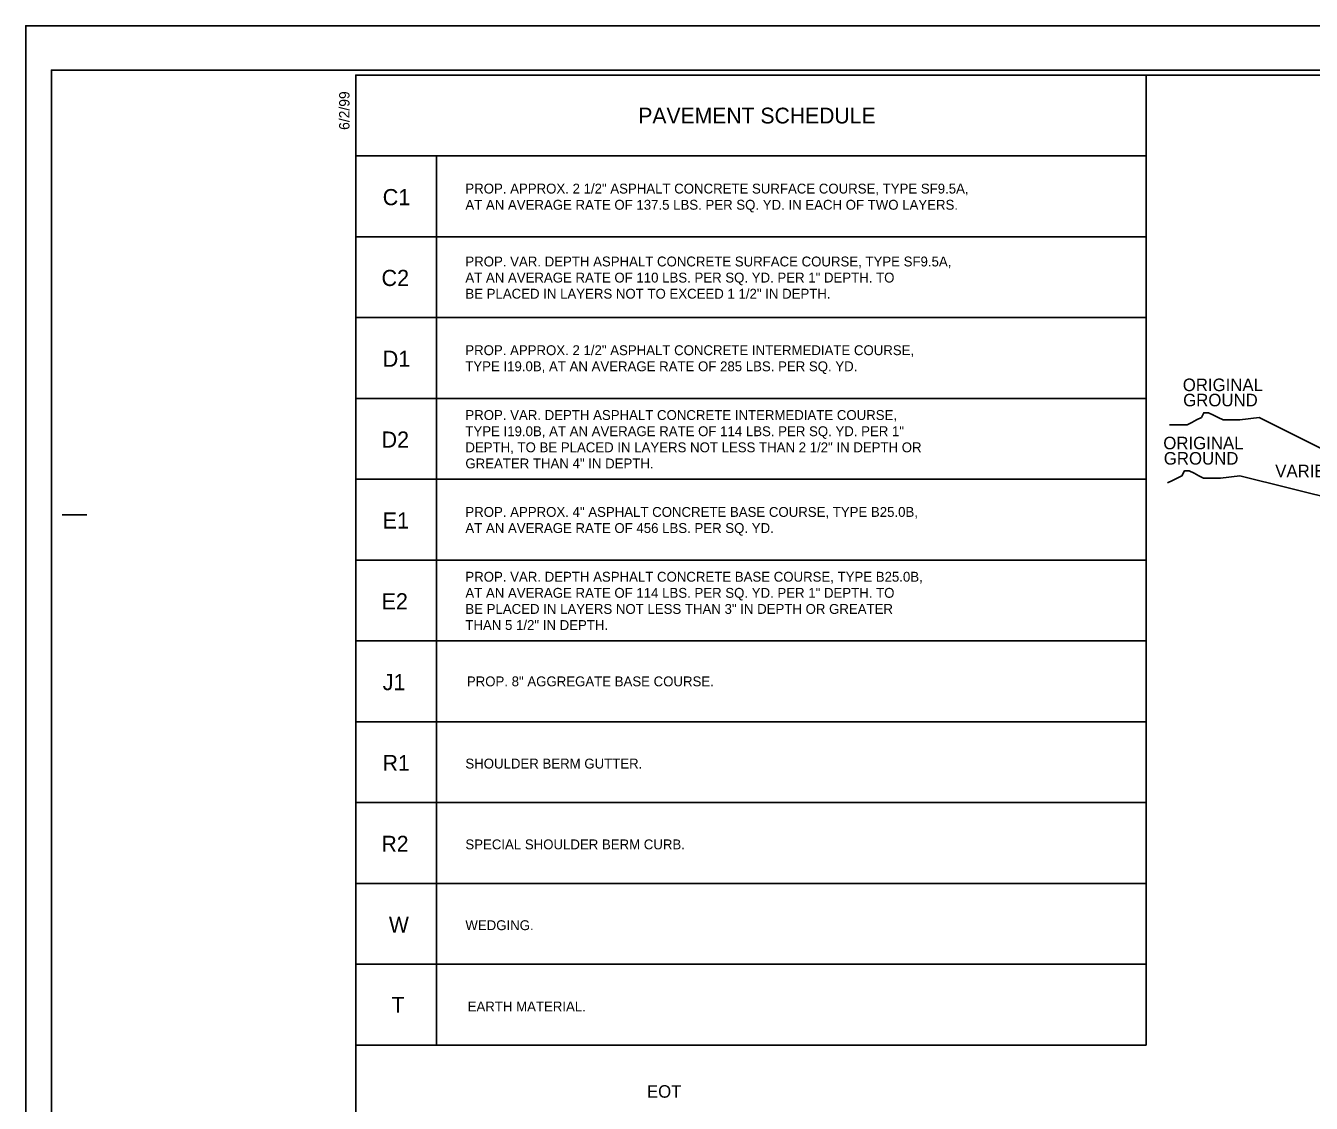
# Model space of a CAD drawing. Extents: x 574067 to 574470, y -53282 to -53062.
# Drawn here: x 574066.9 to 574197, y -53171.2 to -53062.1 of the extents above; entities that cross this region are included whole.
import ezdxf

# ---------------------------------------------------------------- set-up
doc = ezdxf.new("R2010")
doc.units = 0
for name, color, linetype in [('Old_Level_1', 7, 'Continuous'), ('Prop Dimension', 7, 'Continuous'), ('Prop Pavement Schedule Description CELL', 7, 'Continuous'), ('Sheet Cutting Line CELL', 7, 'Continuous'), ('Sheet Plot Border Inside CELL', 7, 'Continuous'), ('Sheet Plot Border Outside CELL', 7, 'Continuous'), ('Sheet Typical CELL', 7, 'Continuous'), ('Typical Slope Point Local CELL', 7, 'Continuous')]:
    doc.layers.add(name, color=color, linetype=linetype)

msp = doc.modelspace()

# ---------------------------------------------------------------- linework, layer by layer
at = {"layer": 'Prop Dimension'}
msp.add_lwpolyline([(574108.51, -53091.67), (574100.33, -53091.67), (574100.33, -53083.49), (574180.33, -53083.49), (574180.33, -53091.67), (574108.51, -53091.67), (574108.51, -53083.49)], dxfattribs=at)
at = {"layer": 'Prop Pavement Schedule Description CELL'}
msp.add_lwpolyline([(574100.33, -53067.12), (574180.33, -53067.12), (574180.33, -53075.31), (574100.33, -53075.31)], close=True, dxfattribs=at)
for points in [[(574108.51, -53083.49), (574100.33, -53083.49), (574100.33, -53075.31), (574180.33, -53075.31), (574180.33, -53083.49), (574108.51, -53083.49), (574108.51, -53075.31)], [(574108.51, -53099.85), (574100.33, -53099.85), (574100.33, -53091.67), (574180.33, -53091.67), (574180.33, -53099.85), (574108.51, -53099.85), (574108.51, -53091.67)], [(574108.51, -53108.03), (574100.33, -53108.03), (574100.33, -53099.85), (574180.33, -53099.85), (574180.33, -53108.03), (574108.51, -53108.03), (574108.51, -53099.85)], [(574108.51, -53116.21), (574100.33, -53116.21), (574100.33, -53108.03), (574180.33, -53108.03), (574180.33, -53116.21), (574108.51, -53116.21), (574108.51, -53108.03)], [(574108.51, -53124.4), (574100.33, -53124.4), (574100.33, -53116.21), (574180.33, -53116.21), (574180.33, -53124.4), (574108.51, -53124.4), (574108.51, -53116.21)], [(574108.51, -53132.58), (574100.33, -53132.58), (574100.33, -53124.4), (574180.33, -53124.4), (574180.33, -53132.58), (574108.51, -53132.58), (574108.51, -53124.4)], [(574108.51, -53140.76), (574100.33, -53140.76), (574100.33, -53132.58), (574180.33, -53132.58), (574180.33, -53140.76), (574108.51, -53140.76), (574108.51, -53132.58)], [(574108.51, -53148.94), (574100.33, -53148.94), (574100.33, -53140.76), (574180.33, -53140.76), (574180.33, -53148.94), (574108.51, -53148.94), (574108.51, -53140.76)], [(574108.51, -53157.12), (574100.33, -53157.12), (574100.33, -53148.94), (574180.33, -53148.94), (574180.33, -53157.12), (574108.51, -53157.12), (574108.51, -53148.94)], [(574108.51, -53165.3), (574100.33, -53165.3), (574100.33, -53157.12), (574180.33, -53157.12), (574180.33, -53165.3), (574108.51, -53165.3), (574108.51, -53157.12)]]:
    msp.add_lwpolyline(points, dxfattribs=at)
at = {"layer": 'Sheet Cutting Line CELL'}
for p, q in [((574403.73, -53062.12), (574066.93, -53062.12)), ((574066.93, -53062.12), (574066.93, -53282.12))]:
    msp.add_line(p, q, dxfattribs=at)
at = {"layer": 'Sheet Plot Border Inside CELL'}
msp.add_lwpolyline([(574402.83, -53066.61), (574069.53, -53066.61), (574069.53, -53277.63), (574402.83, -53277.63)], close=True, dxfattribs=at)
at = {"layer": 'Sheet Plot Border Outside CELL'}
msp.add_lwpolyline([(574403.73, -53062.12), (574066.93, -53062.12), (574066.93, -53282.12), (574403.73, -53282.12)], close=True, dxfattribs=at)
at = {"layer": 'Sheet Typical CELL'}
msp.add_line((574070.63, -53111.62), (574073.13, -53111.62), dxfattribs=at)
msp.add_lwpolyline([(574400.33, -53067.12), (574100.33, -53067.12), (574100.33, -53277.12), (574400.33, -53277.12)], close=True, dxfattribs=at)
at = {"layer": 'Typical Slope Point Local CELL'}
for p in [(574191.76, -53101.79), (574189.8, -53107.68)]:
    msp.add_line(p, (574217.29, -53114.55), dxfattribs=at)
for points in [[(574191.76, -53101.79), (574189.82, -53102.03), (574189.33, -53102.03), (574188.6, -53102.03), (574188.12, -53102.03), (574187.63, -53101.79), (574187.14, -53101.54), (574186.66, -53101.3), (574186.17, -53101.3), (574185.93, -53101.79), (574185.44, -53102.03), (574184.95, -53102.27), (574184.47, -53102.52), (574183.98, -53102.52), (574183.49, -53102.52), (574183.01, -53102.52), (574182.71, -53102.52)], [(574189.8, -53107.68), (574187.85, -53107.92), (574187.37, -53107.92), (574186.64, -53107.92), (574186.15, -53107.92), (574185.66, -53107.68), (574185.18, -53107.43), (574184.69, -53107.19), (574184.21, -53107.19), (574183.96, -53107.68), (574183.48, -53107.92), (574182.99, -53108.16), (574182.5, -53108.41)]]:
    msp.add_lwpolyline(points, dxfattribs=at)

# ---------------------------------------------------------------- texts
at = {"layer": 'Old_Level_1'}
for s, p in [('ORIGINAL ', (574184.04, -53099.11)), ('GROUND', (574184.08, -53100.65)), ('ORIGINAL ', (574182.07, -53105)), ('GROUND', (574182.12, -53106.55)), ('VARIES', (574193.4, -53107.83))]:
    msp.add_text(s, height=1.27, dxfattribs=at).set_placement(p)
at = {"layer": 'Prop Dimension'}
for s, height, p in [('PROP. VAR. DEPTH ASPHALT CONCRETE SURFACE COURSE, TYPE SF9.5A,', 1, (574111.43, -53086.49)), ('C2', 1.633, (574102.94, -53088.47)), ('AT AN AVERAGE RATE OF 110 LBS. PER SQ. YD. PER 1" DEPTH. TO', 1, (574111.43, -53088.12)), ('BE PLACED IN LAYERS NOT TO EXCEED 1 1/2" IN DEPTH.', 1, (574111.43, -53089.75)), ('EOT', 1.266, (574129.81, -53170.63))]:
    msp.add_text(s, height=height, dxfattribs=at).set_placement(p)
at = {"layer": 'Prop Pavement Schedule Description CELL'}
for s, height, p in [('PAVEMENT SCHEDULE', 1.6, (574128.93, -53072.02)), ('C1', 1.633, (574103.06, -53080.29)), ('PROP. APPROX. 2 1/2" ASPHALT CONCRETE SURFACE COURSE, TYPE SF9.5A,', 1, (574111.43, -53079.11)), ('AT AN AVERAGE RATE OF 137.5 LBS. PER SQ. YD. IN EACH OF TWO LAYERS.', 1, (574111.43, -53080.75)), ('PROP. APPROX. 2 1/2" ASPHALT CONCRETE INTERMEDIATE COURSE,', 1, (574111.42, -53095.47)), ('D1', 1.633, (574103.06, -53096.65)), ('TYPE I19.0B, AT AN AVERAGE RATE OF 285 LBS. PER SQ. YD.', 1, (574111.42, -53097.1)), ('PROP. VAR. DEPTH ASPHALT CONCRETE INTERMEDIATE COURSE,', 1, (574111.43, -53102.03)), ('TYPE I19.0B, AT AN AVERAGE RATE OF 114 LBS. PER SQ. YD. PER 1" ', 1, (574111.43, -53103.67)), ('D2', 1.633, (574102.94, -53104.83)), ('DEPTH, TO BE PLACED IN LAYERS NOT LESS THAN 2 1/2" IN DEPTH OR', 1, (574111.43, -53105.3)), ('GREATER THAN 4" IN DEPTH.', 1, (574111.43, -53106.93)), ('E1', 1.633, (574103.06, -53113.02)), ('PROP. APPROX. 4" ASPHALT CONCRETE BASE COURSE, TYPE B25.0B,', 1, (574111.43, -53111.84)), ('AT AN AVERAGE RATE OF 456 LBS. PER SQ. YD.', 1, (574111.43, -53113.47)), ('PROP. VAR. DEPTH ASPHALT CONCRETE BASE COURSE, TYPE B25.0B,', 1, (574111.43, -53118.4)), ('E2', 1.633, (574102.94, -53121.2)), ('AT AN AVERAGE RATE OF 114 LBS. PER SQ. YD. PER 1" DEPTH. TO', 1, (574111.43, -53120.03)), ('BE PLACED IN LAYERS NOT LESS THAN 3" IN DEPTH OR GREATER', 1, (574111.43, -53121.66)), ('THAN 5 1/2" IN DEPTH.', 1, (574111.43, -53123.29)), ('J1', 1.633, (574103.06, -53129.38)), ('PROP. 8" AGGREGATE BASE COURSE.', 1, (574111.58, -53128.99)), ('R1', 1.6, (574103.06, -53137.54)), ('SHOULDER BERM GUTTER.', 1, (574111.43, -53137.31)), ('R2', 1.6, (574102.94, -53145.72)), ('SPECIAL SHOULDER BERM CURB.', 1, (574111.43, -53145.49)), ('W', 1.6, (574103.69, -53153.91)), ('WEDGING.', 1, (574111.43, -53153.67)), ('T', 1.6, (574103.96, -53162.03)), ('EARTH MATERIAL.', 1, (574111.66, -53161.9))]:
    msp.add_text(s, height=height, dxfattribs=at).set_placement(p)
at = {"layer": 'Sheet Typical CELL'}
msp.add_text('6/2/99', height=1.05, rotation=90, dxfattribs=at).set_placement((574099.7, -53072.67))

doc.saveas('drawing.dxf')
